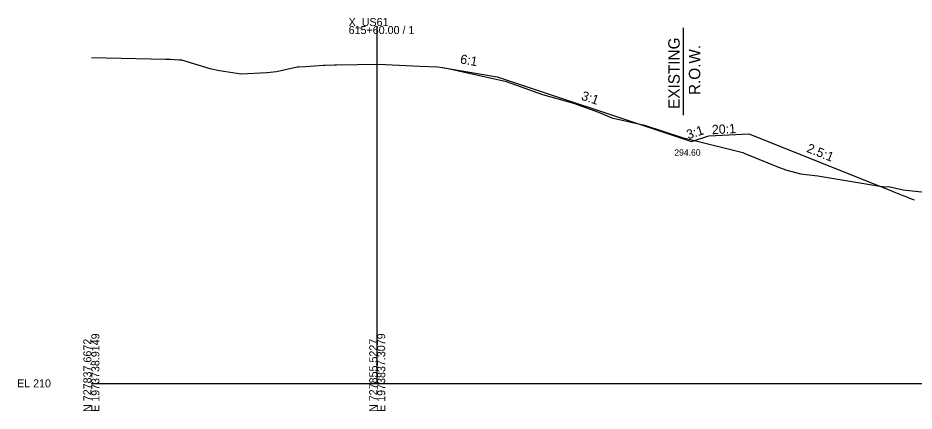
# Model space of a CAD drawing. Extents: x -26 to 1604, y -13 to 9623.
# Drawn here: x -25.7 to 287.8, y 8990.3 to 9127.8 of the extents above; entities that cross this region are included whole.
import ezdxf

# ---------------------------------------------------------------- set-up
doc = ezdxf.new("R2010")
doc.units = 0
for name, color, linetype in [('Draft_XS_Grid', 7, 'Continuous'), ('DTM_X_GROUND', 7, 'Continuous'), ('SLOPE_STAKES_FILL', 7, 'Continuous'), ('XS_CELL', 7, 'Continuous'), ('XS_P_GROUND', 7, 'Continuous'), ('XS_P_TX_DCH', 7, 'Continuous'), ('XS_P_TX_FS_BS', 7, 'Continuous'), ('XS_X_ROW', 7, 'Continuous')]:
    doc.layers.add(name, color=color, linetype=linetype)

msp = doc.modelspace()

# ---------------------------------------------------------------- linework, layer by layer
at = {"layer": 'DTM_X_GROUND'}
msp.add_lwpolyline([(0, 9113.99), (25.96, 9113.44), (27.54, 9113.41), (29.01, 9113.32), (30.7, 9113.22), (31.27, 9113.19), (31.49, 9113.18), (33, 9112.74), (41.41, 9110.2), (44.84, 9109.44), (52.45, 9108.31), (61.43, 9108.75), (64.75, 9109.1), (72.04, 9110.68), (72.45, 9110.74), (74.86, 9110.9), (81.26, 9111.31), (81.75, 9111.31), (85.09, 9111.39), (85.71, 9111.4), (100.4, 9111.63), (114.85, 9111.01), (121.09, 9110.74), (122.89, 9110.47), (124.8, 9110.18), (135.77, 9107.72), (144.77, 9105.71), (147.09, 9104.89), (157.78, 9101.1), (168.64, 9097.97), (177.45, 9094.91), (182.09, 9092.87), (193.48, 9090.28), (206.72, 9086.03), (209.61, 9085.3), (227.88, 9080.77), (228.6, 9080.42), (240.43, 9075.6), (243.3, 9074.53), (248.1, 9073.33), (254.13, 9072.61), (275.18, 9069.06), (277.73, 9068.71), (278.87, 9068.87), (283.98, 9067.73), (305.29, 9065.33)], dxfattribs=at)
at = {"layer": 'XS_CELL'}
for p, q in [((100, 9000), (100, 9125)), ((0, 9000), (100, 9000)), ((100, 9000), (600, 9000))]:
    msp.add_line(p, q, dxfattribs=at)
at = {"layer": 'XS_P_GROUND'}
for points in [[(122, 9110.6), (142, 9107.27)], [(142, 9107.27), (204, 9086.6), (210, 9084.6), (216, 9086.6), (230, 9087.3), (275.81, 9068.98)], [(275.8, 9068.98), (279.65, 9067.45), (280.09, 9067.28), (284.19, 9065.64), (284.91, 9065.36), (287.09, 9064.49), (287.85, 9064.19)]]:
    msp.add_lwpolyline(points, dxfattribs=at)
at = {"layer": 'XS_X_ROW'}
msp.add_line((207, 9124.36), (207, 9093.81), dxfattribs=at)

# ---------------------------------------------------------------- texts
at = {"layer": 'Draft_XS_Grid'}
msp.add_text('-', height=0.0001, dxfattribs=at).set_placement((0, 9000))
at = {"layer": 'SLOPE_STAKES_FILL'}
for p in [(141.96, 9107.21), (203.96, 9086.54), (215.96, 9086.54), (229.96, 9087.24), (209.96, 9084.54)]:
    msp.add_text('X', height=0.12, dxfattribs=at).set_placement(p)
at = {"layer": 'XS_CELL'}
for s, p in [('X_US61', (90, 9125)), ('615+60.00 / 1', (90, 9122.2)), ('EL 210', (-26, 8998.6))]:
    msp.add_text(s, height=2.8, dxfattribs=at).set_placement(p)
for s, p in [('E 1973738.9149', (2.8, 8990)), ('E 1973837.3079', (102.8, 8990)), ('N 727837.6672', (0, 8990)), ('N 727855.5227', (100, 8990))]:
    msp.add_text(s, height=2.8, rotation=90, dxfattribs=at).set_placement(p)
at = {"layer": 'XS_P_GROUND'}
for p in [(121.96, 9110.54), (275.77, 9068.92)]:
    msp.add_text('X', height=0.12, dxfattribs=at).set_placement(p)
at = {"layer": 'XS_P_TX_DCH'}
msp.add_text('294.60', height=2.25, dxfattribs=at).set_placement((203.92, 9079.64))
at = {"layer": 'XS_P_TX_FS_BS'}
for s, rotation, p in [('6:1', 350.5377, (128.86, 9111.93)), ('3:1', 341.5651, (171.16, 9099.31)), ('3:1', 18.4349, (208.81, 9085.36)), ('20:1', 2.8624, (217.15, 9087.14)), ('2.5:1', 338.1986, (249.96, 9081.04))]:
    msp.add_text(s, height=3.24, rotation=rotation, dxfattribs=at).set_placement(p)
at = {"layer": 'XS_X_ROW'}
for s, p in [('EXISTING', (205.82, 9096.03)), ('R.O.W.', (213.02, 9100.87))]:
    msp.add_text(s, height=4, rotation=90, dxfattribs=at).set_placement(p)

doc.saveas('drawing.dxf')
